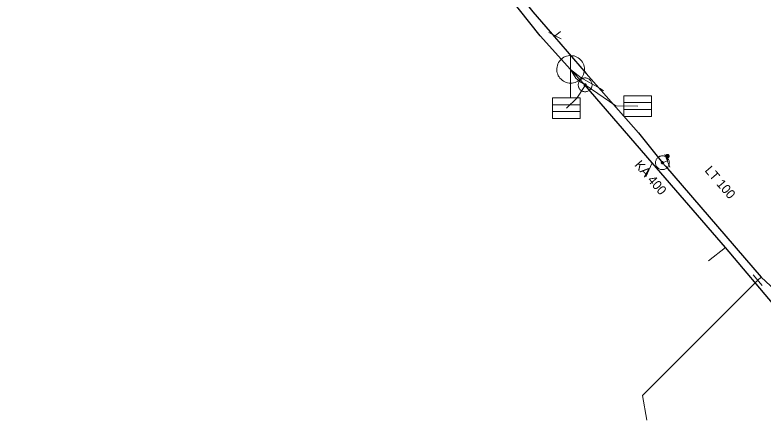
# Model space of a CAD drawing. Extents: x -688432 to -687974, y -973332 to -972704.
# Drawn here: x -688097.1 to -688043, y -972983.5 to -972954.2 of the extents above; entities that cross this region are included whole.
import ezdxf
from ezdxf.enums import TextEntityAlignment as Align

# ---------------------------------------------------------------- set-up
doc = ezdxf.new("R2010")
doc.units = 0
doc.header["$LTSCALE"] = 0.27
for name, color, linetype, lineweight in [('1', 7, 'Continuous', 25), ('11', 7, 'Continuous', 13), ('13', 7, 'Continuous', 13), ('14', 7, 'Continuous', 25), ('17', 7, 'Continuous', 25), ('22', 7, 'Continuous', 13), ('31', 7, 'Continuous', 13), ('34', 7, 'Continuous', 13), ('47', 7, 'Continuous', 13), ('9', 7, 'Continuous', 13)]:
    doc.layers.add(name, color=color, linetype=linetype, lineweight=lineweight)

msp = doc.modelspace()

# ---------------------------------------------------------------- linework, layer by layer
at = {"layer": '11'}
for p, q in [((-688051.44, -972965.94), (-688050.98, -972964.93)), ((-688046.899, -972972.01), (-688045.67, -972971.059))]:
    msp.add_line(p, q, dxfattribs=at)
for points in [[(-688055.829, -972959.3), (-688056.16, -972959.109), (-688056.5, -972958.809), (-688056.879, -972958.18)], [(-688054.5, -972959.739), (-688054.73, -972959.559), (-688056.109, -972958.8), (-688056.879, -972958.18)], [(-688057.18, -972960.989), (-688056.42, -972960.26), (-688055.87, -972959.42), (-688055.829, -972959.3)], [(-688052.02, -972960.84), (-688053.62, -972960.809), (-688055.829, -972959.3)]]:
    msp.add_lwpolyline(points, dxfattribs=at)
at = {"layer": '13'}
msp.add_line((-688058, -972955.75), (-688057.616, -972955.432), dxfattribs=at)
msp.add_lwpolyline([(-688043.35, -972973.42), (-688051.681, -972981.754), (-688051.37, -972983.528)], dxfattribs=at)
at = {"layer": '14', "lineweight": 13}
for p, q in [((-688058.039, -972955.829), (-688058, -972955.75)), ((-688050.239, -972964.93), (-688050.016, -972965.189)), ((-688043.1, -972973.21), (-688043.35, -972973.42))]:
    msp.add_line(p, q, dxfattribs=at)
at = {"layer": '14'}
for points in [[(-688056.879, -972958.18), (-688059.07, -972955.76), (-688062.829, -972951.039), (-688064.66, -972948.89)], [(-688041.899, -972975.539), (-688045.67, -972971.059), (-688050.98, -972964.93), (-688055.91, -972959.239), (-688056.879, -972958.18)]]:
    msp.add_lwpolyline(points, dxfattribs=at)
at = {"layer": '14', "lineweight": 13}
msp.add_lwpolyline([(-688050.239, -972964.93), (-688049.879, -972964.789), (-688049.879, -972964.449)], dxfattribs=at)
at = {"layer": '17'}
for points in [[(-688142.539, -972926.989), (-688136.969, -972927.03), (-688124.52, -972926.469), (-688116.5, -972926.3), (-688115.02, -972926.289), (-688112.359, -972926.21), (-688100.73, -972925.699), (-688087.609, -972926.17), (-688083.969, -972927.539), (-688080.94, -972929.1), (-688078.329, -972931.09), (-688076.37, -972933.14), (-688074.449, -972935.62), (-688070.85, -972940.129), (-688068.85, -972942.57), (-688067.02, -972944.8), (-688063.62, -972948.98), (-688063.329, -972949.34), (-688059.6, -972954.02), (-688058.039, -972955.829), (-688055.76, -972958.48), (-688051.969, -972962.76), (-688050.239, -972964.93)], [(-688050.016, -972965.189), (-688043.1, -972973.21), (-688040.76, -972975.36), (-688034.039, -972978.039), (-688032.41, -972978.5), (-688025.25, -972978.18), (-688016.6, -972977.329), (-688010.039, -972976.26), (-688001.6, -972974.35), (-687996.96, -972972.8), (-687993.41, -972971.309), (-687988.37, -972969.23)]]:
    msp.add_lwpolyline(points, dxfattribs=at)
at = {"layer": '22'}
for p, q in [((-688056.879, -972960.18), (-688056.878, -972957.18)), ((-688058.191, -972960.732), (-688056.191, -972960.732)), ((-688053.031, -972960.583), (-688051.031, -972960.583)), ((-688058.191, -972961.232), (-688056.191, -972961.232)), ((-688053.031, -972961.083), (-688051.031, -972961.083))]:
    msp.add_line(p, q, dxfattribs=at)
for points in [[(-688055.879, -972958.18), (-688055.884, -972958.071), (-688055.902, -972957.963), (-688055.932, -972957.857), (-688055.972, -972957.756), (-688056.024, -972957.659), (-688056.086, -972957.569), (-688056.158, -972957.486), (-688056.238, -972957.412), (-688056.326, -972957.346), (-688056.42, -972957.291), (-688056.52, -972957.246), (-688056.625, -972957.213), (-688056.732, -972957.191), (-688056.841, -972957.181), (-688056.951, -972957.183), (-688057.059, -972957.197), (-688057.166, -972957.222), (-688057.269, -972957.259), (-688057.367, -972957.308), (-688057.459, -972957.366), (-688057.545, -972957.435), (-688057.622, -972957.512), (-688057.691, -972957.598), (-688057.75, -972957.69), (-688057.798, -972957.788), (-688057.835, -972957.891), (-688057.861, -972957.998), (-688057.875, -972958.106), (-688057.878, -972958.216), (-688057.868, -972958.325), (-688057.847, -972958.432), (-688057.813, -972958.536), (-688057.769, -972958.636), (-688057.714, -972958.731), (-688057.648, -972958.819), (-688057.574, -972958.899), (-688057.491, -972958.971), (-688057.401, -972959.033), (-688057.305, -972959.085), (-688057.203, -972959.126), (-688057.098, -972959.156), (-688056.99, -972959.174), (-688056.88, -972959.18), (-688056.771, -972959.174), (-688056.663, -972959.156), (-688056.558, -972959.127), (-688056.456, -972959.086), (-688056.359, -972959.034), (-688056.269, -972958.972), (-688056.186, -972958.901), (-688056.111, -972958.821), (-688056.046, -972958.733), (-688055.99, -972958.639), (-688055.946, -972958.539), (-688055.912, -972958.435), (-688055.89, -972958.327), (-688055.88, -972958.218)], [(-688053.031, -972960.083), (-688051.031, -972960.083), (-688051.031, -972961.583), (-688053.031, -972961.583)], [(-688058.191, -972960.232), (-688056.191, -972960.232), (-688056.191, -972961.732), (-688058.191, -972961.732)]]:
    msp.add_lwpolyline(points, close=True, dxfattribs=at)
at = {"layer": '31'}
for points in [[(-688055.329, -972959.3), (-688055.332, -972959.248), (-688055.34, -972959.196), (-688055.354, -972959.146), (-688055.372, -972959.097), (-688055.396, -972959.05), (-688055.425, -972959.006), (-688055.458, -972958.966), (-688055.495, -972958.929), (-688055.535, -972958.896), (-688055.579, -972958.867), (-688055.626, -972958.843), (-688055.675, -972958.825), (-688055.725, -972958.811), (-688055.777, -972958.803), (-688055.829, -972958.8), (-688055.881, -972958.803), (-688055.933, -972958.811), (-688055.984, -972958.825), (-688056.032, -972958.843), (-688056.079, -972958.867), (-688056.123, -972958.896), (-688056.164, -972958.929), (-688056.201, -972958.966), (-688056.234, -972959.006), (-688056.262, -972959.05), (-688056.286, -972959.097), (-688056.305, -972959.146), (-688056.318, -972959.196), (-688056.326, -972959.248), (-688056.329, -972959.3), (-688056.326, -972959.352), (-688056.318, -972959.404), (-688056.305, -972959.455), (-688056.286, -972959.503), (-688056.262, -972959.55), (-688056.234, -972959.594), (-688056.201, -972959.635), (-688056.164, -972959.672), (-688056.123, -972959.705), (-688056.079, -972959.733), (-688056.032, -972959.757), (-688055.984, -972959.776), (-688055.933, -972959.789), (-688055.881, -972959.797), (-688055.829, -972959.8), (-688055.777, -972959.797), (-688055.725, -972959.789), (-688055.675, -972959.776), (-688055.626, -972959.757), (-688055.579, -972959.733), (-688055.535, -972959.705), (-688055.495, -972959.672), (-688055.458, -972959.635), (-688055.425, -972959.594), (-688055.396, -972959.55), (-688055.372, -972959.503), (-688055.354, -972959.455), (-688055.34, -972959.404), (-688055.332, -972959.352)], [(-688055.747, -972959.3), (-688055.747, -972959.291), (-688055.749, -972959.283), (-688055.751, -972959.275), (-688055.754, -972959.267), (-688055.758, -972959.259), (-688055.763, -972959.252), (-688055.768, -972959.245), (-688055.774, -972959.239), (-688055.781, -972959.234), (-688055.788, -972959.229), (-688055.796, -972959.225), (-688055.804, -972959.222), (-688055.812, -972959.22), (-688055.82, -972959.218), (-688055.829, -972959.218), (-688055.838, -972959.218), (-688055.846, -972959.22), (-688055.854, -972959.222), (-688055.862, -972959.225), (-688055.87, -972959.229), (-688055.877, -972959.234), (-688055.884, -972959.239), (-688055.89, -972959.245), (-688055.896, -972959.252), (-688055.9, -972959.259), (-688055.904, -972959.267), (-688055.907, -972959.275), (-688055.909, -972959.283), (-688055.911, -972959.291), (-688055.911, -972959.3), (-688055.911, -972959.309), (-688055.909, -972959.317), (-688055.907, -972959.325), (-688055.904, -972959.333), (-688055.9, -972959.341), (-688055.896, -972959.348), (-688055.89, -972959.355), (-688055.884, -972959.361), (-688055.877, -972959.367), (-688055.87, -972959.371), (-688055.862, -972959.375), (-688055.854, -972959.378), (-688055.846, -972959.38), (-688055.838, -972959.382), (-688055.829, -972959.382), (-688055.82, -972959.382), (-688055.812, -972959.38), (-688055.804, -972959.378), (-688055.796, -972959.375), (-688055.788, -972959.371), (-688055.781, -972959.367), (-688055.774, -972959.361), (-688055.768, -972959.355), (-688055.763, -972959.348), (-688055.758, -972959.341), (-688055.754, -972959.333), (-688055.751, -972959.325), (-688055.749, -972959.317), (-688055.747, -972959.309)]]:
    msp.add_lwpolyline(points, close=True, dxfattribs=at)
at = {"layer": '34'}
for p, q in [((-688058.447, -972955.526), (-688057.553, -972955.974)), ((-688050.06, -972964.323), (-688049.698, -972965.255)), ((-688043.028, -972973.802), (-688043.671, -972973.036))]:
    msp.add_line(p, q, dxfattribs=at)
at = {"layer": '47'}
for points in [[(-688049.927, -972965.32), (-688049.888, -972965.286), (-688049.852, -972965.247), (-688049.822, -972965.205), (-688049.795, -972965.16), (-688049.773, -972965.112), (-688049.757, -972965.062), (-688049.746, -972965.011), (-688049.74, -972964.959), (-688049.739, -972964.908), (-688049.744, -972964.855), (-688049.755, -972964.803), (-688049.771, -972964.754), (-688049.791, -972964.706), (-688049.817, -972964.66), (-688049.848, -972964.618), (-688049.882, -972964.579), (-688049.921, -972964.543), (-688049.964, -972964.512), (-688050.008, -972964.486), (-688050.056, -972964.464), (-688050.106, -972964.448), (-688050.157, -972964.436), (-688050.209, -972964.43), (-688050.261, -972964.43), (-688050.313, -972964.435), (-688050.365, -972964.446), (-688050.415, -972964.461), (-688050.462, -972964.482), (-688050.508, -972964.508), (-688050.55, -972964.539), (-688050.589, -972964.573), (-688050.625, -972964.612), (-688050.656, -972964.654), (-688050.682, -972964.699), (-688050.704, -972964.747), (-688050.721, -972964.796), (-688050.732, -972964.847), (-688050.738, -972964.899), (-688050.738, -972964.952), (-688050.733, -972965.004), (-688050.722, -972965.056), (-688050.707, -972965.105), (-688050.686, -972965.153), (-688050.66, -972965.199), (-688050.629, -972965.241), (-688050.595, -972965.28), (-688050.556, -972965.316), (-688050.515, -972965.347), (-688050.469, -972965.373), (-688050.421, -972965.395), (-688050.372, -972965.412), (-688050.321, -972965.423), (-688050.269, -972965.428), (-688050.217, -972965.429), (-688050.164, -972965.424), (-688050.112, -972965.413), (-688050.064, -972965.398), (-688050.015, -972965.377), (-688049.969, -972965.351)], [(-688050.187, -972964.994), (-688050.18, -972964.988), (-688050.175, -972964.981), (-688050.17, -972964.975), (-688050.166, -972964.968), (-688050.162, -972964.959), (-688050.16, -972964.951), (-688050.157, -972964.943), (-688050.157, -972964.934), (-688050.157, -972964.926), (-688050.157, -972964.917), (-688050.159, -972964.909), (-688050.162, -972964.9), (-688050.165, -972964.893), (-688050.169, -972964.885), (-688050.174, -972964.878), (-688050.18, -972964.871), (-688050.187, -972964.866), (-688050.193, -972964.861), (-688050.2, -972964.857), (-688050.209, -972964.853), (-688050.217, -972964.851), (-688050.225, -972964.848), (-688050.234, -972964.848), (-688050.243, -972964.847), (-688050.251, -972964.848), (-688050.259, -972964.85), (-688050.268, -972964.853), (-688050.275, -972964.856), (-688050.283, -972964.86), (-688050.29, -972964.865), (-688050.297, -972964.871), (-688050.302, -972964.878), (-688050.307, -972964.884), (-688050.311, -972964.891), (-688050.315, -972964.9), (-688050.318, -972964.907), (-688050.32, -972964.916), (-688050.32, -972964.925), (-688050.321, -972964.934), (-688050.32, -972964.942), (-688050.318, -972964.95), (-688050.315, -972964.959), (-688050.312, -972964.966), (-688050.308, -972964.974), (-688050.303, -972964.981), (-688050.297, -972964.988), (-688050.29, -972964.993), (-688050.284, -972964.998), (-688050.277, -972965.002), (-688050.268, -972965.006), (-688050.261, -972965.009), (-688050.252, -972965.011), (-688050.243, -972965.011), (-688050.235, -972965.011), (-688050.226, -972965.011), (-688050.218, -972965.009), (-688050.209, -972965.006), (-688050.202, -972965.003), (-688050.194, -972964.999)]]:
    msp.add_lwpolyline(points, close=True, dxfattribs=at)
at = {"layer": '9'}
for points in [[(-688050.005, -972964.449), (-688050.005, -972964.462), (-688050.002, -972964.475), (-688050, -972964.488), (-688049.995, -972964.5), (-688049.989, -972964.512), (-688049.982, -972964.523), (-688049.973, -972964.533), (-688049.963, -972964.543), (-688049.953, -972964.551), (-688049.943, -972964.558), (-688049.931, -972964.564), (-688049.919, -972964.569), (-688049.906, -972964.572), (-688049.892, -972964.574), (-688049.88, -972964.576), (-688049.867, -972964.575), (-688049.853, -972964.573), (-688049.841, -972964.57), (-688049.828, -972964.565), (-688049.816, -972964.559), (-688049.806, -972964.552), (-688049.796, -972964.544), (-688049.786, -972964.534), (-688049.777, -972964.524), (-688049.771, -972964.513), (-688049.765, -972964.501), (-688049.76, -972964.489), (-688049.757, -972964.476), (-688049.755, -972964.463), (-688049.752, -972964.45), (-688049.754, -972964.437), (-688049.755, -972964.424), (-688049.759, -972964.411), (-688049.764, -972964.399), (-688049.769, -972964.387), (-688049.777, -972964.376), (-688049.784, -972964.366), (-688049.794, -972964.356), (-688049.804, -972964.348), (-688049.816, -972964.341), (-688049.828, -972964.335), (-688049.84, -972964.33), (-688049.853, -972964.327), (-688049.865, -972964.325), (-688049.879, -972964.324), (-688049.892, -972964.324), (-688049.904, -972964.326), (-688049.918, -972964.329), (-688049.929, -972964.334), (-688049.941, -972964.34), (-688049.953, -972964.347), (-688049.963, -972964.355), (-688049.973, -972964.365), (-688049.98, -972964.375), (-688049.988, -972964.386), (-688049.994, -972964.398), (-688049.999, -972964.41), (-688050.002, -972964.423), (-688050.004, -972964.436)], [(-688049.985, -972964.449), (-688049.985, -972964.46), (-688049.983, -972964.471), (-688049.98, -972964.482), (-688049.977, -972964.492), (-688049.972, -972964.502), (-688049.966, -972964.511), (-688049.958, -972964.52), (-688049.951, -972964.528), (-688049.941, -972964.535), (-688049.933, -972964.541), (-688049.923, -972964.546), (-688049.913, -972964.55), (-688049.902, -972964.553), (-688049.891, -972964.556), (-688049.88, -972964.556), (-688049.869, -972964.556), (-688049.858, -972964.554), (-688049.847, -972964.551), (-688049.837, -972964.547), (-688049.826, -972964.542), (-688049.818, -972964.536), (-688049.809, -972964.529), (-688049.801, -972964.521), (-688049.794, -972964.512), (-688049.788, -972964.503), (-688049.782, -972964.493), (-688049.779, -972964.483), (-688049.776, -972964.472), (-688049.774, -972964.461), (-688049.772, -972964.45), (-688049.772, -972964.439), (-688049.774, -972964.428), (-688049.777, -972964.417), (-688049.782, -972964.407), (-688049.787, -972964.397), (-688049.793, -972964.388), (-688049.799, -972964.379), (-688049.808, -972964.371), (-688049.816, -972964.364), (-688049.826, -972964.358), (-688049.836, -972964.353), (-688049.845, -972964.349), (-688049.857, -972964.346), (-688049.867, -972964.344), (-688049.879, -972964.344), (-688049.89, -972964.343), (-688049.901, -972964.345), (-688049.912, -972964.348), (-688049.921, -972964.352), (-688049.931, -972964.357), (-688049.941, -972964.363), (-688049.95, -972964.37), (-688049.958, -972964.378), (-688049.965, -972964.387), (-688049.97, -972964.396), (-688049.975, -972964.406), (-688049.98, -972964.416), (-688049.983, -972964.427), (-688049.985, -972964.438)], [(-688049.966, -972964.449), (-688049.966, -972964.458), (-688049.965, -972964.467), (-688049.962, -972964.476), (-688049.958, -972964.484), (-688049.955, -972964.492), (-688049.95, -972964.5), (-688049.943, -972964.507), (-688049.938, -972964.513), (-688049.931, -972964.519), (-688049.923, -972964.524), (-688049.914, -972964.528), (-688049.907, -972964.531), (-688049.897, -972964.534), (-688049.889, -972964.535), (-688049.88, -972964.537), (-688049.87, -972964.536), (-688049.862, -972964.535), (-688049.853, -972964.532), (-688049.845, -972964.529), (-688049.837, -972964.525), (-688049.828, -972964.52), (-688049.821, -972964.514), (-688049.816, -972964.508), (-688049.809, -972964.501), (-688049.804, -972964.493), (-688049.801, -972964.485), (-688049.798, -972964.477), (-688049.794, -972964.468), (-688049.794, -972964.459), (-688049.791, -972964.45), (-688049.793, -972964.441), (-688049.794, -972964.432), (-688049.796, -972964.423), (-688049.799, -972964.415), (-688049.804, -972964.407), (-688049.809, -972964.399), (-688049.815, -972964.392), (-688049.821, -972964.386), (-688049.828, -972964.38), (-688049.836, -972964.375), (-688049.843, -972964.371), (-688049.852, -972964.368), (-688049.86, -972964.365), (-688049.87, -972964.364), (-688049.879, -972964.363), (-688049.887, -972964.363), (-688049.897, -972964.364), (-688049.906, -972964.367), (-688049.914, -972964.37), (-688049.921, -972964.374), (-688049.929, -972964.379), (-688049.936, -972964.385), (-688049.943, -972964.391), (-688049.948, -972964.398), (-688049.953, -972964.406), (-688049.958, -972964.414), (-688049.961, -972964.422), (-688049.963, -972964.431), (-688049.965, -972964.44)], [(-688049.946, -972964.449), (-688049.946, -972964.456), (-688049.945, -972964.463), (-688049.943, -972964.47), (-688049.941, -972964.476), (-688049.938, -972964.482), (-688049.934, -972964.488), (-688049.929, -972964.494), (-688049.924, -972964.499), (-688049.919, -972964.503), (-688049.913, -972964.507), (-688049.907, -972964.51), (-688049.901, -972964.513), (-688049.894, -972964.514), (-688049.887, -972964.517), (-688049.88, -972964.517), (-688049.872, -972964.517), (-688049.865, -972964.515), (-688049.858, -972964.514), (-688049.853, -972964.511), (-688049.845, -972964.508), (-688049.841, -972964.504), (-688049.835, -972964.5), (-688049.83, -972964.495), (-688049.826, -972964.489), (-688049.821, -972964.483), (-688049.818, -972964.477), (-688049.816, -972964.471), (-688049.814, -972964.464), (-688049.813, -972964.457), (-688049.811, -972964.45), (-688049.811, -972964.443), (-688049.813, -972964.436), (-688049.815, -972964.429), (-688049.818, -972964.423), (-688049.821, -972964.416), (-688049.825, -972964.411), (-688049.828, -972964.405), (-688049.833, -972964.4), (-688049.84, -972964.396), (-688049.845, -972964.392), (-688049.852, -972964.389), (-688049.858, -972964.386), (-688049.865, -972964.384), (-688049.872, -972964.383), (-688049.879, -972964.383), (-688049.886, -972964.383), (-688049.892, -972964.383), (-688049.899, -972964.385), (-688049.906, -972964.388), (-688049.912, -972964.391), (-688049.918, -972964.395), (-688049.924, -972964.399), (-688049.929, -972964.404), (-688049.933, -972964.41), (-688049.936, -972964.415), (-688049.94, -972964.422), (-688049.943, -972964.428), (-688049.943, -972964.435), (-688049.946, -972964.442)], [(-688049.926, -972964.449), (-688049.926, -972964.454), (-688049.926, -972964.459), (-688049.924, -972964.464), (-688049.923, -972964.468), (-688049.921, -972964.473), (-688049.918, -972964.477), (-688049.914, -972964.48), (-688049.911, -972964.484), (-688049.907, -972964.487), (-688049.904, -972964.49), (-688049.899, -972964.492), (-688049.894, -972964.494), (-688049.89, -972964.495), (-688049.885, -972964.497), (-688049.88, -972964.497), (-688049.875, -972964.497), (-688049.87, -972964.496), (-688049.865, -972964.495), (-688049.86, -972964.493), (-688049.855, -972964.491), (-688049.852, -972964.488), (-688049.848, -972964.485), (-688049.845, -972964.481), (-688049.842, -972964.478), (-688049.838, -972964.474), (-688049.837, -972964.469), (-688049.835, -972964.465), (-688049.833, -972964.46), (-688049.833, -972964.455), (-688049.831, -972964.45), (-688049.831, -972964.445), (-688049.833, -972964.44), (-688049.833, -972964.435), (-688049.836, -972964.431), (-688049.838, -972964.426), (-688049.841, -972964.422), (-688049.843, -972964.418), (-688049.847, -972964.415), (-688049.85, -972964.412), (-688049.855, -972964.409), (-688049.86, -972964.407), (-688049.864, -972964.405), (-688049.869, -972964.404), (-688049.874, -972964.403), (-688049.879, -972964.403), (-688049.884, -972964.403), (-688049.889, -972964.404), (-688049.894, -972964.404), (-688049.897, -972964.406), (-688049.902, -972964.408), (-688049.907, -972964.411), (-688049.909, -972964.414), (-688049.914, -972964.417), (-688049.916, -972964.421), (-688049.919, -972964.425), (-688049.921, -972964.43), (-688049.924, -972964.434), (-688049.924, -972964.439), (-688049.926, -972964.444)], [(-688049.906, -972964.449), (-688049.906, -972964.452), (-688049.907, -972964.455), (-688049.906, -972964.457), (-688049.904, -972964.46), (-688049.904, -972964.463), (-688049.902, -972964.465), (-688049.899, -972964.467), (-688049.897, -972964.469), (-688049.896, -972964.471), (-688049.894, -972964.473), (-688049.891, -972964.475), (-688049.887, -972964.476), (-688049.886, -972964.476), (-688049.882, -972964.477), (-688049.88, -972964.477), (-688049.877, -972964.477), (-688049.874, -972964.477), (-688049.87, -972964.476), (-688049.869, -972964.475), (-688049.865, -972964.474), (-688049.864, -972964.472), (-688049.86, -972964.47), (-688049.858, -972964.468), (-688049.858, -972964.466), (-688049.855, -972964.464), (-688049.855, -972964.461), (-688049.853, -972964.458), (-688049.853, -972964.456), (-688049.852, -972964.453), (-688049.85, -972964.45), (-688049.852, -972964.447), (-688049.852, -972964.444), (-688049.853, -972964.441), (-688049.853, -972964.439), (-688049.855, -972964.436), (-688049.857, -972964.434), (-688049.858, -972964.431), (-688049.86, -972964.429), (-688049.863, -972964.428), (-688049.865, -972964.426), (-688049.867, -972964.425), (-688049.87, -972964.424), (-688049.872, -972964.423), (-688049.875, -972964.423), (-688049.879, -972964.422), (-688049.882, -972964.423), (-688049.885, -972964.422), (-688049.887, -972964.424), (-688049.89, -972964.424), (-688049.892, -972964.425), (-688049.894, -972964.427), (-688049.897, -972964.428), (-688049.899, -972964.43), (-688049.901, -972964.433), (-688049.902, -972964.435), (-688049.904, -972964.438), (-688049.904, -972964.44), (-688049.906, -972964.443), (-688049.906, -972964.446)], [(-688049.887, -972964.449), (-688049.887, -972964.451), (-688049.887, -972964.451), (-688049.886, -972964.451), (-688049.886, -972964.453), (-688049.887, -972964.454), (-688049.885, -972964.454), (-688049.885, -972964.454), (-688049.885, -972964.456), (-688049.885, -972964.456), (-688049.884, -972964.457), (-688049.882, -972964.457), (-688049.882, -972964.457), (-688049.882, -972964.458), (-688049.88, -972964.458), (-688049.88, -972964.458), (-688049.879, -972964.458), (-688049.877, -972964.458), (-688049.877, -972964.457), (-688049.877, -972964.457), (-688049.875, -972964.457), (-688049.875, -972964.456), (-688049.875, -972964.456), (-688049.874, -972964.455), (-688049.874, -972964.455), (-688049.872, -972964.454), (-688049.872, -972964.453), (-688049.87, -972964.452), (-688049.87, -972964.452), (-688049.87, -972964.451), (-688049.87, -972964.45), (-688049.87, -972964.449), (-688049.87, -972964.448), (-688049.87, -972964.448), (-688049.872, -972964.447), (-688049.872, -972964.446), (-688049.872, -972964.445), (-688049.872, -972964.445), (-688049.874, -972964.444), (-688049.874, -972964.444), (-688049.875, -972964.443), (-688049.875, -972964.443), (-688049.877, -972964.442), (-688049.877, -972964.442), (-688049.877, -972964.442), (-688049.879, -972964.442), (-688049.88, -972964.442), (-688049.88, -972964.442), (-688049.88, -972964.442), (-688049.882, -972964.443), (-688049.882, -972964.442), (-688049.884, -972964.444), (-688049.884, -972964.444), (-688049.885, -972964.444), (-688049.885, -972964.444), (-688049.886, -972964.446), (-688049.886, -972964.447), (-688049.886, -972964.448), (-688049.887, -972964.448), (-688049.887, -972964.449)]]:
    msp.add_lwpolyline(points, close=True, dxfattribs=at)

# ---------------------------------------------------------------- texts
at = {"layer": '1'}
for s, p in [('KA 400', (-688051.3445, -972966.2189)), ('KA 400', (-688051.3445, -972966.2189)), ('KA 400', (-688051.3445, -972966.2189)), ('KA 400', (-688051.3445, -972966.2189)), ('KA 400', (-688051.3445, -972966.2189)), ('LT 100', (-688046.3102, -972966.561)), ('LT 100', (-688046.3102, -972966.561)), ('LT 100', (-688046.3102, -972966.561)), ('LT 100', (-688046.3102, -972966.561)), ('LT 100', (-688046.3102, -972966.561))]:
    msp.add_text(s, height=0.6667, rotation=311, dxfattribs=at).set_placement(p, align=Align.CENTER)

doc.saveas('drawing.dxf')
